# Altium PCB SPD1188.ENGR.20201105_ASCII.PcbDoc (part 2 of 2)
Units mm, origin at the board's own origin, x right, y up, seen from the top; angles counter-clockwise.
Board outline 110.11 x 115.1 mm, 2 copper layers (Top Layer, Bottom Layer); 167 components, 110 nets, 467 pads, 496 vias.
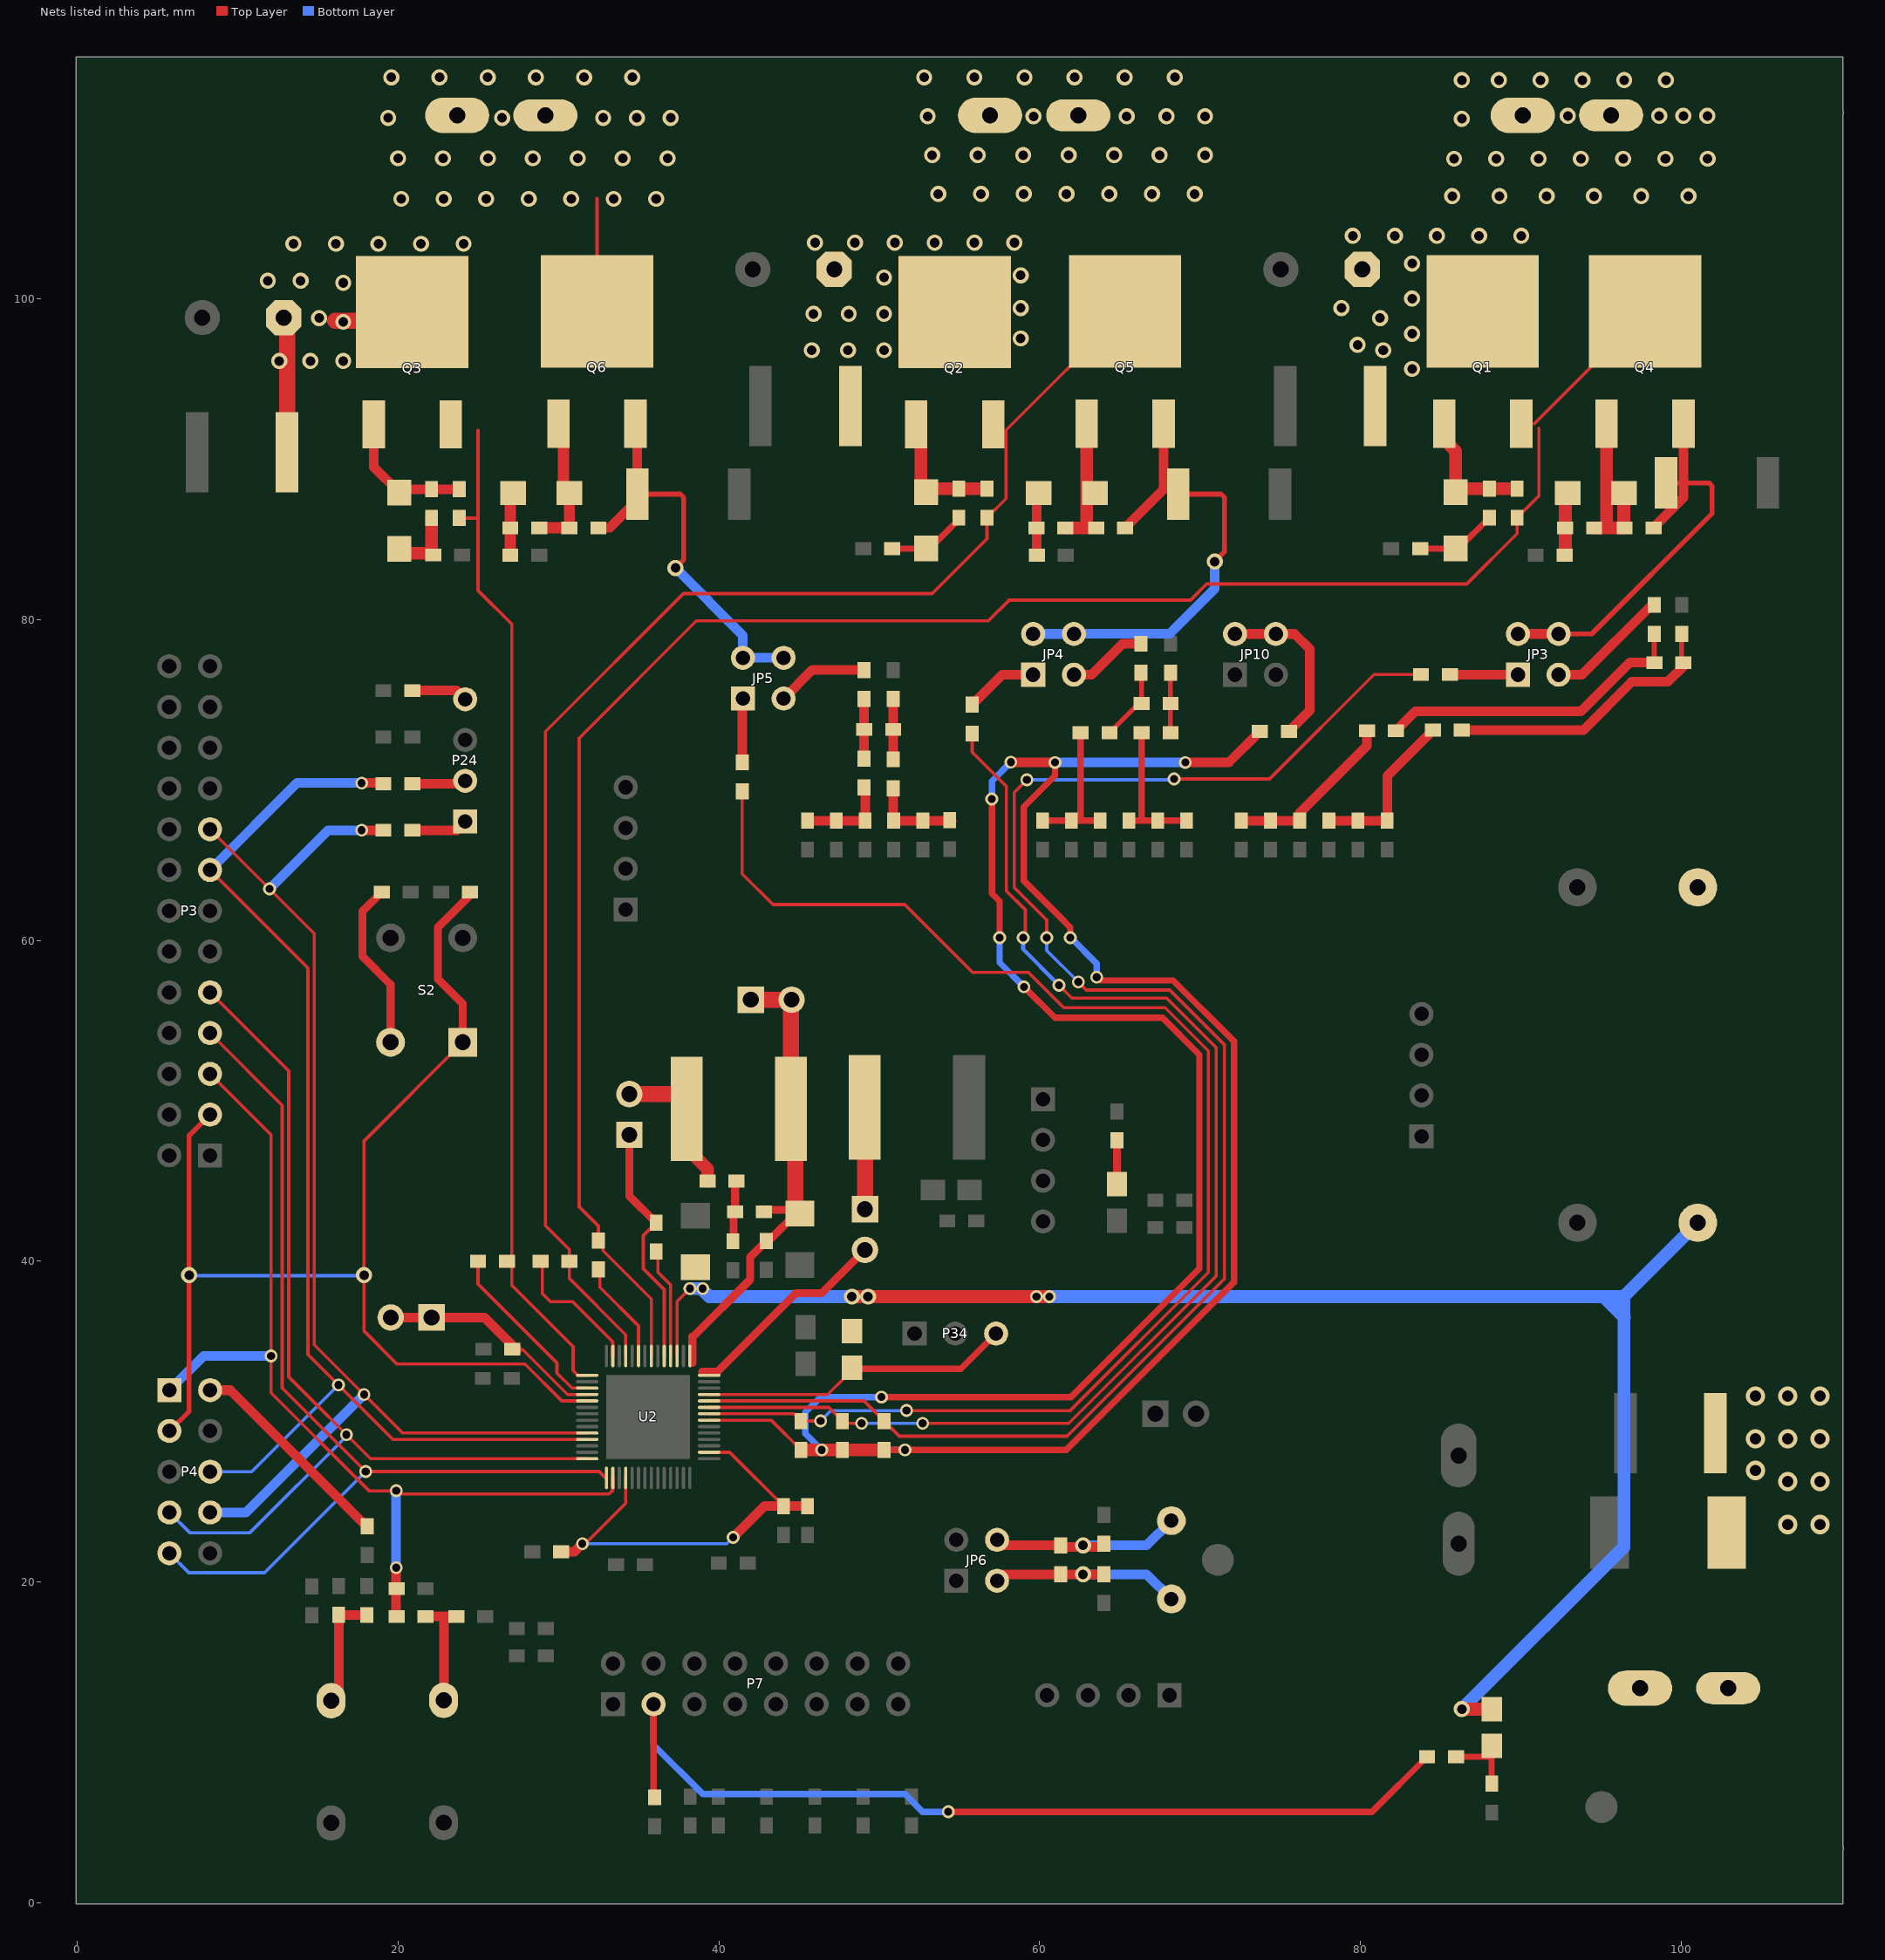
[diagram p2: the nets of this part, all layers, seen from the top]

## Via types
v1: diameter 0.8, hole 0.5, Top Layer to Bottom Layer, tented both sides, 215 vias
v2: diameter 1, hole 0.6, Top Layer to Bottom Layer, 161 vias
v3: diameter 1, hole 0.6, Top Layer to Bottom Layer, tented both sides, 71 vias
v4: diameter 1.2, hole 0.7, Top Layer to Bottom Layer, tented both sides, 33 vias
v5: diameter 0.8, hole 0.5, Top Layer to Bottom Layer, 16 vias

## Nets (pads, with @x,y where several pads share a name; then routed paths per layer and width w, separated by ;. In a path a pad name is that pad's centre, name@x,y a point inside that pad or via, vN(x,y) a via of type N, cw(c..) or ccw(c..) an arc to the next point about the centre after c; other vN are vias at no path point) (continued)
NetC58_1: C58.1 C60.1 R86.1 | length 3.7
  Top Layer w0.5: C60.1@40.93,41.38 C58.1@40.93,43.08 ; C58.1@41.02,43.08 41.02,44.92 R86.1@41.1,45
NetC130_1: C130.1 R133.1 R135.2 | length 19.6
  Top Layer w0.3: C130.1@98.29,77.31 R135.2@98.29,79.1
  Top Layer w0.6: R133.1@82.19,73.06 83.39,74.26 93.72,74.26 96.76,77.3 C130.1@98.28,77.3
NetC130_2: C130.2 R132.1 R134.2 | length 17.4
  Top Layer w0.3: C130.2@100,77.4 R134.2@100,79.1
  Top Layer w0.6: R132.1@86.3,73.1 93.88,73.1 96.89,76.11 99.14,76.11 100.1,77.07 C130.2@100.1,77.3
NetC140_1: C140.1 R143.1 R145.2 | length 4.7
  Top Layer w0.3: R143.1@64.35,72.94 66.17,74.76 C140.1@66.35,74.76 66.35,76.63 R145.2@66.3,76.68
NetC140_2: C140.2 R142.1 R144.2 | length 3.7
  Top Layer w0.3: R142.1@68.15,72.94 R144.2@68.15,76.68
NetC150_1: C150.1 R153.1 R155.2 | length 3.7
  Top Layer w0.6: R153.1@49.05,71.32 R155.2@49.05,75.04
NetC150_2: C150.2 R152.1 R154.2 | length 3.8
  Top Layer w0.6: R152.1@50.87,71.28 R154.2@50.87,75.04
NetC232_1: C232.1 R130.1 R132.2 R136.1 | length 10.5
  Top Layer w0.6: C232.1@78.011,67.45 R136.1@79.831,67.45 R130.1@81.65,67.45 81.65,70.25 R132.2@84.5,73.1
NetC233_2: C233.2 R131.1 R133.2 R194.1 | length 11
  Top Layer w0.6: R131.1@72.554,67.45 R194.1@74.373,67.45 C233.2@76.192,67.45 76.192,67.932 80.39,72.13 R133.2@80.39,73.06
NetC234_1: C234.1 R140.2 R143.2 R147.1 | length 9
  Top Layer w0.4: R140.2@60.184,67.45 C234.1@63.766,67.45 ; 62.55,67.49 R143.2@62.55,72.94
NetC235_2: C235.2 R141.1 R142.2 R146.1 | length 9
  Top Layer w0.4: C235.2@65.558,67.45 R141.1@69.14,67.45 ; 66.35,67.49 R142.2@66.35,72.94
NetC236_1: C236.1 R150.1 R152.2 R156.1 | length 5.6
  Top Layer w0.6: R152.2@50.87,69.48 50.87,67.498 50.918,67.45 R156.1@52.712,67.45 R150.1@54.506,67.45
NetC237_2: C237.2 R151.1 R153.2 R157.1 | length 5.7
  Top Layer w0.6: R151.1@45.535,67.45 R157.1@47.329,67.45 C237.2@49.123,67.45 49.123,69.447 R153.2@49.05,69.52
NetD1_1: D1.1 Q1.1 R2.2 RP1.1 | length 8.2
  Top Layer w0.8: Q1.1@85.2,92.19 85.2,91.2 85.916,90.484 D1.1@85.916,87.925 ; D1.1@86.125,88.135 RP1.1@89.741,88.135
NetD1_2: D1.2 R1.2 R2.1 | length 5.1
  Top Layer w0.4: R1.2@83.7,84.4 86.081,84.4 R2.1@88.016,86.335
NetD2_1: D2.1 Q2.1 R4.2 RP2.1 | length 7.9
  Top Layer w0.8: Q2.1@52.3,92.15 52.6,91.85 52.6,88.24 D2.1@52.8,88.04 ; D2.1@53.125,88.135 RP2.1@56.716,88.135
NetD2_2: D2.2 R3.2 R4.1 | length 5
  Top Layer w0.4: R3.2@50.8,84.4 53.141,84.4 R4.1@55.016,86.275
NetD3_1: D3.1 Q3.1 R6.2 Rp3.1 | length 8.4
  Top Layer w0.6: Q3.1@18.5,92.15 18.5,89.494 D3.1@20.094,87.9 ; D3.1@20.304,88.11 Rp3.1@23.826,88.11
NetD3_2: D3.2 R5.2 R6.1 | length 3.9
  Top Layer w0.8: D3.2@20.374,84.121 22.11,84.121 R6.1@22.11,86.31
NetD4_1: D4.1 Q4.1 R8.2 Rp4.1 | length 10.5
  Top Layer w0.8: R8.2@94.541,85.7 Rp4.1@96.441,85.7 ; 95.316,85.716 Q4.1@95.316,92.19 ; Rp4.1@96.391,85.75 D4.1@96.391,87.863
NetD4_2: D4.2 R7.2 R8.1 | length 3.7
  Top Layer w0.8: R7.2@92.741,84 D4.2@92.741,87.713
NetD5_1: D5.1 Q5.1 R10.2 Rp5.1 | length 7.8
  Top Layer w0.8: R10.2@61.593,85.7 62.916,85.7 ; 62.916,85.716 Q5.1@62.916,92.19
NetD5_2: D5.2 R9.2 R10.1 | length 3.7
  Top Layer w0.6: R9.2@59.816,84 D5.2@59.816,87.744
NetD6_1: D6.1 Q6.1 R12.2 Rp6.1 | length 8
  Top Layer w0.7: R12.2@28.81,85.7 Rp6.1@30.7,85.7 30.693,85.707 D6.1@30.693,87.583 ; D6.1@30.316,88.54 Q6.1@30.316,92.19 ; D6.1@30.693,87.863 D6.1@30.693,87.583 ; D6.1@30.91,87.8 D6.1@30.693,87.583
NetD6_2: D6.2 R11.2 R12.1 | length 3.7
  Top Layer w0.7: R11.2@27.01,84 D6.2@27.01,87.68
NetD7_2: D7.2 R16.2 | length 2.7
  Top Layer w0.5: D7.2@64.81,44.813 R16.2@64.81,47.53
NetJP2_1: JP2.1 L2.1 | length 7.1
  Top Layer w1: L2.1@48.59,49.59 L2.1@49.09,49.09 ; L2.1@49.09,49.59 L2.1@49.09,49.09 ; JP2.1@49.11,43.25 49.11,47.28 49.09,47.3 L2.1@49.09,49.09
NetJP3_1: JP3.1 R187.1 | length 4.2
  Top Layer w0.6: R187.1@85.55,76.56 89.78,76.56 JP3.1@89.79,76.55
NetJP3_3: JP3.3 R135.1 | length 7.8
  Top Layer w0.6: JP3.3@92.33,76.55 93.79,76.55 98.14,80.9 R135.1@98.29,80.9
NetJP4_1: JP4.1 R188.1 | length 4.6
  Top Layer w0.6: R188.1@55.79,74.68 57.66,76.55 JP4.1@59.59,76.55
NetJP4_3: JP4.3 R145.1 | length 5
  Top Layer w0.6: JP4.3@62.13,76.55 63.23,76.55 65.16,78.48 R145.1@66.3,78.48
NetJP5_1: JP5.1 R189.1 | length 3.7
  Top Layer w0.6: R189.1@41.46,71.32 JP5.1@41.46,75.02
NetJP5_3: JP5.3 R155.1 | length 5.7
  Top Layer w0.6: JP5.3@44.04,75.06 45.82,76.84 R155.1@49.05,76.84
NetJP10_2: JP10.2 JP10.4 R137.1 | length 10.7
  Top Layer w0.6: JP10.2@72.17,79.09 JP10.4@74.71,79.09 75.87,79.09 76.81,78.15 76.81,74.31 R137.1@75.52,73.02
NetP4_2: P4.2 R68.1 | length 13.3
  Top Layer w0.6: P4.2@8.31,31.97 9.557,31.97 18.027,23.5 R68.1@18.1,23.5
NetP24_4: P24.4 R24.1 | length 3.5
  Top Layer w0.6: R24.1@20.9,75.565 23.655,75.565 P24.4@24.2,75.02
NetR31_2: R31.2 R32.2 S3.1 | length 7.3
  Top Layer w0.6: R31.2@21.76,17.89 R32.2@23.646,17.89 ; S3.1@22.88,12.4 22.88,17.816
NetR61_2: R61.2 R77.2 S1.1 | length 7.5
  Top Layer w0.6: S1.1@15.87,12.38 15.87,12.7 16.32,13.15 R61.2@16.32,17.97 18.06,17.97 R77.2@18.07,17.96
NetR66_1: R66.1 S2.2 | length 10.6
  Top Layer w0.5: R66.1@19,63 17.8,61.8 17.8,59 19.55,57.25 S2.2@19.55,53.65
NetR440_1: R440.1 R441.2 R442.2 | length 4.5
  Top Layer w0.381: R442.2@85.93,9.13 R440.1@88.09,9.13 ; R441.2@88.16,7.45 R440.1@88.16,9.807
PX_U: C13.2 Q3.3 Q6.2 Rp3.2 U1.1 U2.43 | length 70.3
  Top Layer w0.2: Rp3.2@23.826,86.31 24.99,86.31 ; 25,91.774 25,81.8 27.1,79.7 27.1,38.5 30.92,34.68 30.92,33.19 31.21,32.9 U2.43@31.8,32.9 ; Q6.2@32.416,99.19 32.416,106.24
  other v2: 20.216,106.2 22.863,106.2 25.51,106.2 28.158,106.2 30.805,106.2 33.453,106.2 36.1,106.2 20.016,108.722 22.816,108.722 25.616,108.722 28.416,108.722 31.216,108.722 34.016,108.722 36.816,108.722 19.4,111.245 26.5,111.245 32.8,111.245 34.9,111.245 37,111.245 19.6,113.767 22.603,113.767 25.606,113.767 28.609,113.767 31.613,113.767 34.616,113.767
PX_V: C14.2 Q2.3 Q5.2 RP2.2 U2.39 V1.1 | length 91.2
  Top Layer w0.2: U2.39@34.2,34.1 34.2,35.42 30.7,38.92 C14.2@30.7,40 30.7,40.723 29.2,42.223 29.2,73 37.8,81.6 53.3,81.6 56.716,85.016 RP2.2@56.716,86.335 57.9,87.519 57.9,91.774 Q5.2@65.316,99.19
  other v2: 53.672,106.5 56.336,106.5 59,106.5 61.664,106.5 64.328,106.5 66.992,106.5 69.656,106.5 53.3,108.922 56.133,108.922 58.967,108.922 61.8,108.922 64.633,108.922 67.467,108.922 70.3,108.922 53.016,111.345 59.616,111.345 65.416,111.345 67.9,111.345 70.3,111.345 52.8,113.767 55.923,113.767 59.046,113.767 62.169,113.767 65.293,113.767 68.416,113.767
PX_W: C15.2 Q1.3 Q4.2 RP1.2 U2.35 W1.1 | length 121.1
  Top Layer w0.2: U2.35@35.8,34.1 35.8,37.65 32.79,40.66 32.79,41.01 C15.2@32.5,41.3 32.5,42.2 31.3,43.4 31.3,72.6 38.6,79.9 56.8,79.9 58.1,81.2 69.4,81.2 70.4,82.2 86.6,82.2 89.741,85.341 RP1.2@89.741,86.335 91.1,87.694 91.1,91.906 ; 90.816,92.19 97.716,99.09 Q4.2@97.716,99.19
  other v2: 85.7,106.367 88.643,106.367 91.586,106.367 94.529,106.367 97.472,106.367 100.416,106.367 85.816,108.7 88.449,108.7 91.082,108.7 93.716,108.7 96.349,108.7 98.982,108.7 101.616,108.7 86.3,111.189 92.9,111.367 98.6,111.367 100.1,111.367 101.6,111.367 86.3,113.6 88.603,113.6 91.206,113.6 93.809,113.6 96.412,113.6 99.016,113.6
RU: JP5.2 JP5.4 Q6.3 R15.2 Rp6.2 | length 25
  Top Layer w0.3: R15.2@34.925,87.8 37.6,87.8 37.8,87.6 37.8,83.7 v3(37.3,83.2)
  Top Layer w0.6: Rp6.2@32.5,85.7 33.214,85.7 R15.2@34.925,87.411 ; Q6.3@34.816,92.19 34.925,92.081 R15.2@34.925,87.8
  Bottom Layer w0.6: v3(37.3,83.2) 41.5,79 JP5.2@41.5,77.6 JP5.4@44.04,77.6
RV: JP4.2 JP4.4 Q5.3 R14.2 Rp5.2 | length 28.9
  Top Layer w0.3: R14.2@68.625,87.8 71.3,87.8 71.5,87.6 71.5,84.2 v3(70.9,83.6)
  Top Layer w0.6: Rp5.2@65.316,85.7 67.716,88.1 Q5.3@67.716,92.19
  Bottom Layer w0.6: JP4.2@59.59,79.09 JP4.4@62.13,79.09 62.14,79.1 68.1,79.1 70.9,81.9 v3(70.9,83.6)
RW: JP3.2 JP3.4 Q4.3 R13.2 Rp4.2 | length 27.1
  Top Layer w0.3: JP3.4@92.33,79.09 94.39,79.09 101.9,86.6 101.9,88.3 101.7,88.5 R13.2@99.025,88.5
  Top Layer w0.6: JP3.2@89.79,79.09 JP3.4@92.33,79.09 ; Rp4.2@98.241,85.7 100.116,87.575 Q4.3@100.116,92.19
RXD: P3.15 P4.6 R73.2 U2.53 | length 75.9
  Top Layer w0.2: P3.15@8.3,64.38 14.4,58.28 14.4,34.2 19.7,28.9 U2.53@31.8,28.9
  Top Layer w0.6: v1(17.75,69.8) 18.922,69.8 19.022,69.7 19.082,69.76 19.142,69.7 R73.2@19.2,69.758
  Bottom Layer w0.2: P4.6@8.31,26.89 10.89,26.89 v1(16.3,32.3)
  Bottom Layer w0.6: P3.15@8.3,64.38 13.72,69.8 v1(17.75,69.8) ; P3.15@8.422,64.258 P3.15@8.48,64.2
SNS_GND: C131.2 C191.2 C192.2 R137.2 U2.21 | length 174.2
  Top Layer w0.2: U2.21@39.4,30.1 43.27,30.1 43.32,30.05 ; 44.233,29.137 43.32,30.05 ; C131.2@45.12,28.25 43.32,30.05
  Top Layer w0.4: v1(50.14,31.54) 57.041,31.54 61.94,31.54 69.945,39.545 69.945,52.871 67.649,55.167 60.948,55.167 v1(59.016,57.1) ; C191.2@50.3,28.25 56.85,28.25 61.65,28.25 72.1,38.7 72.1,53.7 68.3,57.5 63.75,57.5 v1(63.55,57.7) ; v1(57.016,68.8) 57.016,62.911 57.5,62.427 v1(57.5,60.167) ; v1(60.95,71.08) 60.95,70.25 59.02,68.32 59,68.3 59,63.7 61.2,61.5 61.9,60.8 v1@61.9,60.2
  Top Layer w0.6: v1(58.2,71.1) 58.22,71.08 v1(60.95,71.08) ; v1(69.07,71.08) 71.78,71.08 R137.2@73.72,73.02
  Top Layer w0.8: C131.2@45.12,28.25 C192.2@47.71,28.25 C191.2@50.3,28.25
  Bottom Layer w0.4: v1(50.14,31.54) 46.34,31.54 45.4,30.6 45.4,29.265 v1(46.415,28.25) v1(51.6,28.25) ; v1(57.016,68.8) 57.016,69.916 v1(58.2,71.1) ; v1(57.5,60.167) 57.5,58.616 v1(59.016,57.1) ; v1@61.9,60.2 63.55,58.55 63.55,57.85 v1@63.625,57.775
  Bottom Layer w0.6: v1(60.95,71.08) v1(69.07,71.08)
  other v1: 61.9,60.167
SNSP_U: C131.1 R189.2 U2.22 | length 87.9
  Top Layer w0.2: U2.22@39.4,30.5 44.67,30.5 C131.1@45.12,30.05 v1(46.35,30.05) ; R189.2@41.46,69.52 41.46,64.15 43.38,62.23 51.586,62.23 55.816,58 59.3,58 61.5,55.8 67.815,55.8 70.51,53.105 70.51,39.31 61.9,30.7 v1(51.7,30.7)
  Bottom Layer w0.2: v1(46.35,30.05) 47,30.7 v1(51.7,30.7)
SNSP_V: C192.1 R188.2 U2.23 | length 79.5
  Top Layer w0.2: U2.23@39.4,30.9 46.86,30.9 C192.1@47.71,30.05 ; C192.1@47.97,29.9 v1(48.9,29.9) ; v1(52.7,29.9) 61.807,29.9 71,39.093 71,53.308 67.908,56.4 62,56.4 v1(61.2,57.2) ; R188.2@55.885,72.615 55.97,72.7 R188.2@55.79,72.88 55.79,71.726 57.926,69.59 57.926,63.074 59.1,61.9 v1@59.1,60.2
  Bottom Layer w0.2: v1(48.9,29.9) v1(52.7,29.9) ; v1@59.1,60.167 v1@59.1,60.2 ; v1@61.1,57.3 v1(61.2,57.2)
  Bottom Layer w0.25: v1(58.967,60.167) 58.967,59.433 v1@61.1,57.3
SNSP_W: C191.1 R187.2 U2.24 | length 104.5
  Top Layer w0.2: U2.24@39.4,31.3 49.05,31.3 C191.1@50.3,30.05 51.25,29.1 61.7,29.1 71.5,38.9 71.5,53.501 68.101,56.9 62.9,56.9 v1(62.4,57.4) ; v1(59.2,70) 58.416,69.216 58.416,63.285 60.433,61.268 60.433,60.367 v1@60.6,60.2 ; v1(68.37,70.05) 74.32,70.05 80.83,76.56 R187.2@83.75,76.56
  Bottom Layer w0.2: v1(59.2,70) 68.32,70 v1(68.37,70.05) ; v1(60.433,60.167) v1@60.433,60.033 ; v1@60.6,60.2 v1@60.433,60.033 ; v1(62.4,57.4) 60.433,59.367 v1@60.433,60.033
SW3: JP2.2 U2.28 | length 13.3
  Top Layer w0.5: 38.96,33.11 39.91,33.11 44.82,38.02 46.42,38.02 JP2.2@49.11,40.71
SWCK: P3.7 P4.9 U2.1 | length 61.8
  Top Layer w0.2: P3.7@8.3,54.22 12.8,49.72 12.8,32.1 v1(18,26.9) 32.56,26.9 U2.1@32.96,26.5
  Bottom Layer w0.2: P4.9@5.77,21.81 6.98,20.6 11.7,20.6 v1(18,26.9)
SWDIO: P3.9 P4.7 U2.56 | length 60.8
  Top Layer w0.2: P3.9@8.3,56.76 13.2,51.86 13.2,32.8 18.3,27.7 U2.56@31.8,27.7
  Bottom Layer w0.2: P4.7@5.77,24.35 7.03,23.09 10.79,23.09 16.8,29.1 v1(16.8,29.2)
SWG: C51.1 JP1.1 U2.33 | length 15.6
  Top Layer w0.2: C51.1@36.09,42.69 36.09,42.39 35.3,41.6 35.3,39.537 36.6,38.237 U2.33@36.6,34.1
  Top Layer w0.5: JP1.1@34.43,47.88 34.43,44.07 C51.1@36.1,42.4
SWG1: JP1.2 L1.1 R86.2 | length 12.1
  Top Layer w0.5: L1.1@38.22,47.9 L1.1@38.22,49.19
  Top Layer w0.8: L1.1@37.92,46.68 37.92,49.42 L1.1@38,49.5 38,47.05 39.3,45.75 R86.2@39.3,45
  Top Layer w1: JP1.2@35.03,50.42 L1.1@37.92,50.42
TRSTN: CL8.1 P3.5 P4.1 R31.1 U2.2 | length 61.3
  Top Layer w0.2: P3.5@8.3,51.68 12.1,47.88 12.1,31.8 18.2,25.7 v1(19.9,25.7) 20.1,25.5 33.166,25.5 33.4,25.734 U2.2@33.4,26.5
  Top Layer w0.6: v1(19.9,20.91) 19.9,17.883 R31.1@19.923,17.86
  Bottom Layer w0.6: P4.1@5.77,31.97 7.9,34.1 v1(12.1,34.1) ; v1(19.9,20.91) v1(19.9,25.7)
TXD: P3.17 P4.8 R74.2 U2.52 | length 75.4
  Top Layer w0.2: P3.17@8.3,66.92 14.8,60.42 14.8,34.8 20.3,29.3 U2.52@31.8,29.3
  Top Layer w0.6: v1(17.75,66.86) 19.015,66.86 19.055,66.9 R74.2@19.1,66.855
  Bottom Layer w0.6: P4.8@8.31,24.35 10.55,24.35 v1(17.9,31.7) ; v1(12.01,63.21) 15.66,66.86 v1(17.75,66.86)
UART_RXD: P24.2 R73.1 | length 3.4
  Top Layer w0.6: R73.1@20.9,69.758 24.018,69.758 P24.2@24.2,69.94
UART_TXD: P24.1 R74.1 | length 3.5
  Top Layer w0.6: R74.1@20.9,66.855 23.655,66.855 P24.1@24.2,67.4
VBAT: C1.1 C2.1 C4.1 C5.1 C6.1 C9.1 C70.1 C72.1 C79.2 E1.1 E2.1 Q1.2 Q2.2 Q3.2 R440.2 U2.31 Vin+.1 ZD1.1 | length 120
  Top Layer w0.2: U2.31@37.4,34.1 37.4,37.5 v1(38.2,38.3)
  Top Layer w0.8: v3(48.3,37.8) v3(49.3,37.8) v1(59.8,37.8) v1(60.6,37.8) ; v3(86.3,12.1) 86.307,12.093 R440.2@88.16,12.093
  Top Layer w1: C6.1@13.1,90.4 C9.1@13.1,98.6 ; 16.1,98.6 22.326,98.6 Q3.2@22.916,99.19
  Bottom Layer w0.8: v1(38.2,38.3) 38.9,38.3 39.4,37.8 v3(48.3,37.8) v3(49.3,37.8) ; v1(59.8,37.8) v1(60.6,37.8) 96.4,37.8 ; v3(86.3,12.1) 96.4,22.2 96.4,36.516 ; 95.174,37.741 96.4,36.516 ; 96.416,36.5 96.4,36.516 ; E1.1@101,42.4 96.4,37.8 ; 96.4,36.516 96.4,37.8
  other v1: 39,38.3
  other v2: 83.2,95.6 12.616,96.1 14.558,96.1 16.6,96.1 45.8,96.767 48.05,96.767 50.3,96.767 81.4,96.767 79.8,97.1 58.816,97.5 83.2,97.789 16.6,98.533 15.1,98.767 81.2,98.767 45.9,99.034 48.1,99.034 50.3,99.034 78.8,99.4 58.816,99.401 83.2,99.978 16.6,100.967 11.9,101.1 13.95,101.1 50.3,101.301 58.816,101.434 83.2,102.167 13.5,103.4 16.15,103.4 18.8,103.4 21.45,103.4 24.1,103.4 46,103.467 48.483,103.467 50.966,103.467 53.449,103.467 55.933,103.467 58.416,103.467 79.5,103.9 82.125,103.9 84.75,103.9 87.375,103.9 90,103.9
  other v4: 106.608,23.6 108.616,23.6 106.608,26.267 108.616,26.267 104.6,26.967 104.6,28.933 106.608,28.933 108.616,28.933 104.6,31.6 106.608,31.6 108.616,31.6
VBAT_DIV: CL420.2 P7.3 R442.1 | length 59.6
  Top Layer w0.4: P7.3@35.94,12.4 35.94,6.66 CL420.2@36,6.6 ; v1@54.4,5.7 80.7,5.7 R442.1@84.13,9.13
  Bottom Layer w0.4: P7.3@35.94,12.4 35.94,9.86 39,6.8 51.6,6.8 52.7,5.7 v1(54.3,5.7)
VBOOT_U: C13.1 U2.45 | length 11.3
  Top Layer w0.2: C13.1@25,40 25,38.59 29.92,33.67 29.92,33.03 30.85,32.1 U2.45@31.8,32.1
VBOOT_V: C14.1 U2.41 | length 8.5
  Top Layer w0.2: C14.1@29,40 29,38 29.51,37.49 30.9,37.49 33.4,34.99 U2.41@33.4,34.1
VBOOT_W: C15.1 U2.37 | length 6.4
  Top Layer w0.2: C15.1@32.6,39.5 32.6,38.38 35,35.98 U2.37@35,34.1
VBOOTG: C51.2 U2.32 | length 7.1
  Top Layer w0.2: C51.2@36.2,40.9 36.2,39.33 37,38.53 U2.32@37,34.1
VCAP12: C25.2 CL53.2 CL54.2 U2.4 U2.16 | length 27.7
  Top Layer w0.2: v1@31.593,22.307 34.2,24.914 U2.4@34.2,26.5 ; U2.16@39.4,28.1 40.68,28.1 CL53.2@44.03,24.75
  Top Layer w0.6: C25.2@30.18,21.9 31,21.9 v1(31.5,22.4) ; v1(40.9,22.8) 42.85,24.75 CL53.2@43.957,24.75 ; CL53.2@44.03,24.75 CL54.2@45.53,24.75
  Bottom Layer w0.2: v1(31.5,22.4) 40.5,22.4 v1(40.9,22.8)
VCP: C79.1 P34.3 U2.25 | length 18.7
  Top Layer w0.2: U2.25@39.4,31.7 46.785,31.7 C79.1@47.942,32.858
  Top Layer w0.4: C79.1@48.495,33.3 55.08,33.3 P34.3@57.28,35.5
VDD5: C54.2 P38.1 P38.2 U2.46 | length 14.2
  Top Layer w0.2: C54.2@27.445,34.5 27.79,34.5 30.59,31.7 U2.46@31.8,31.7
  Top Layer w0.6: P38.2@19.56,36.5 19.57,36.49 25.41,36.49 27.4,34.5 C54.2@27.445,34.5
VDDG: C58.2 C62.2 C71.1 L1.2 P36.1 P36.2 U2.29 | length 28.8
  Top Layer w0.5: 38.35,33.665 38.35,35.31 ; 38.415,35.315 41.96,38.86 41.96,40.26 C62.2@42.96,41.26 ; C58.2@42.8,43.08 42.92,43.2 C71.1@44.88,43.2 ; C62.2@43.1,41.26 C71.1@44.96,43.12
  Top Layer w1: P36.1@42,56.3 P36.2@44.46,56.3 ; L1.2@44.5,47.83 44.768,47.562 C71.1@44.768,43.032 ; L1.2@44.5,49.5 P36.2@44.5,56.26 ; C71.1@44.88,43.2 C71.1@44.96,43.12 ; C71.1@45.048,43.032 C71.1@45.108,42.972 ; P36.2@44.46,56.3 P36.2@44.5,56.26 ; P36.2@44.46,56.3 P36.2@44.54,56.3 P36.2@44.5,56.26
XIN: CL65.2 JP6.3 R102.1 Y1.1 | length 13.1
  Top Layer w0.6: JP6.3@57.34,19.9 JP6.3@57.44,20 ; JP6.3@57.34,20.1 57.74,20.5 R102.1@61.3,20.5 CL65.2@64,20.5
  Bottom Layer w0.6: v3(62.7,20.5) 66.66,20.5 Y1.1@68.2,18.96
XIO: CL66.2 JP6.4 R102.2 Y1.2 | length 13.1
  Top Layer w0.6: JP6.4@57.34,22.44 57.7,22.44 57.84,22.3 R102.2@61.2,22.3 ; R102.2@61.3,22.3 R102.2@61.2,22.3 ; CL66.2@64,22.4 63.8,22.2 61.3,22.2 R102.2@61.2,22.3
  Bottom Layer w0.6: v3(62.7,22.3) 66.66,22.3 Y1.2@68.2,23.84
XRSTN: CL3.2 P3.3 P4.3 S2.1 U2.47 | length 78.7
  Top Layer w0.2: S2.1@24.05,53.65 17.9,47.5 17.9,39.1 17.9,35.649 19.949,33.6 27.92,33.6 30.22,31.3 U2.47@31.8,31.3
  Top Layer w0.3: P4.3@5.77,29.43 7,30.66 v3(7,39.14) 7,47.84 P3.3@8.3,49.14
  Top Layer w0.5: S2.1@24.05,53.65 24.05,56.05 22.5,57.6 22.5,60.8 24.5,62.8 CL3.2@24.5,63
  Bottom Layer w0.2: v3(7,39.14) 7.04,39.1 v3@17.9,39.1
  other v3: 17.9,39.14
pads on no net: P3.19 P4.5 P7.1 S2.3 S2.4

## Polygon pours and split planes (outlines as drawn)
GND on Top Layer "Bottom Layer-W" (hatched 90Degree grid 0.2 track 0.2, remove dead copper, pour order 55): 72.8,104.4 72.8,85.5 73.5,84.8 77.333,84.8 77.9,85.367 77.9,86.3 77.9,95.4 76.9,96.4 76.9,99.1 76.9,104.4 76.3,105 75.8,105 73.4,105
RV on Top Layer "Bottom Layer-W" (hatched 90Degree grid 0.2 track 0.2, remove dead copper, pour order 53): 65.9,86.45 65.9,93.6 66.2,93.9 66.3,94 70.2,94 70.8,93.4 70.8,86 70.2,85.4 65.8,85.4 65.6,85.6 65.6,85.984
PX_V on Top Layer "Bottom Layer-W" (hatched 90Degree grid 0.2 track 0.2, remove dead copper, pour order 52): 55.6,91 55.6,94.4 55.8,94.6 56.2,95 56.8,95 58.5,95 60.2,96.7 60.2,104 59.3,104.9 58.7,105.5 53.8,105.5 53,106.3 52.1,107.2 52.1,109.3 52.1,113.9 52.8,114.6 55.1,114.6 68.6,114.6 70.4,112.8 70.8,112.4 70.8,96.3 70.8,96.2 70,95.4 69.3,94.7 67.4,94.7 62.2,94.7 61.1,93.6 61.1,92 61.1,90.6 60.2,89.7 59.5,89.7 58.4,89.7 57.9,89.2 57.4,89.7 56.9,89.7 56.1,89.7 55.6,90.2
VBAT on Top Layer "Bottom Layer-W" (hatched 90Degree grid 0.2 track 0.2, remove dead copper, pour order 51): 45.1,87.5 45.1,103.6 45.7,104.2 51,104.2 58.6,104.2 59.4,103.4 59.4,97.2 58,95.8 57.7,95.8 51.8,95.8 50.7,94.7 50.7,87.5 49.8,86.6 47.3,86.6 46,86.6
RU on Top Layer "Bottom Layer-W" (hatched 90Degree grid 0.2 track 0.2, remove dead copper, pour order 49): 33.5,86.2 33.5,93.4 33.8,93.7 34,93.9 34.9,93.9 36.6,93.9 37,93.5 37.2,93.3 37.2,85.5 36.6,84.9 34.7,84.9 34.2,85.4 32.7,85.4
GND on Top Layer "Bottom Layer-W" (hatched 90Degree grid 0.2 track 0.2, remove dead copper, pour order 47): 38.9,88 38.9,105.3 39.9,106.3 42.8,106.3 43.8,105.3 44.2,104.9 44.2,99.1 44.2,85.7 43.4,84.9 41.8,84.9 39.7,84.9 38.9,85.7
PX_U on Top Layer "Bottom Layer-W" (hatched 90Degree grid 0.2 track 0.2, remove dead copper, pour order 43): 25,84.9 24.9,84.9 23.8,86 23.826,86.026 23.826,86.31 23.826,86.326 24.5,87 24.8,87.3 24.8,89 24.4,89.4 23.5,89.4 22.6,89.4 22.2,89.8 22.2,91.3 22.2,93.3 22.3,93.4 22.7,93.8 23.7,93.8 26.4,96.5 26.4,103.8 24.7,105.5 20.1,105.5 19,106.6 18.3,107.3 18.3,109.6 18.3,113.3 18.5,113.5 19.5,114.5 22.6,114.5 34.9,114.5 36.4,113 37.7,111.7 37.7,100.8 37.7,96.3 36.6,95.2 36,94.6 28.9,94.6 28.3,94 28.3,92.1 28.3,90.4 28.1,90.2 27.8,89.9 27.4,89.9 26,89.9 25.4,89.3 25.3,89.2 25.3,88.6 25.3,81.1 25,81.4 25,82
VBAT on Top Layer "Bottom Layer-W" (hatched 90Degree grid 0.2 track 0.2, remove dead copper, pour order 42): 11.3,87.6 11.3,102.2 12.7,103.6 13.5,104.4 18.6,104.4 24.5,104.4 25.4,103.5 25.4,96.5 23.6,94.7 17.8,94.7 17,93.9 17,87.7 16.8,87.5 16.2,86.9 14.8,86.9 12,86.9
AGND on Top Layer "Bottom Layer-No Net 1" (hatched 90Degree grid 0.203 track 0.203, remove dead copper, pour order 39): 33.47,18.51 33.61,18.65 34.18,18.65 34.34,18.65 34.93,19.24 34.93,21.17 34.93,21.38 35.08,21.53 35.77,22.22 35.77,22.27 35.77,18.37 35.367,17.967 35.3,17.9 34.91,17.9 33.42,17.9 33.25,18.07
GND on Top Layer "Top Layer-No Net" (hatched 90Degree grid 0.2 track 0.2, remove dead copper, pour order 63): 54.016,68.78 54.143,68.78 54.92,68.78 55.3,68.4 55.3,67.567 55.3,61.4 55.7,61 55.933,60.767 56.4,60.767 56.686,60.767 56.816,60.897 57.016,61.097 57.016,61.5 57.016,62.752 56.8,62.967 56.8,66.967 56.8,70.067 54.3,72.567 53.63,71.897 53.63,70.88 53.63,69.32 53.74,69.21
AGND on Top Layer "Top Layer-No Net" (hatched 90Degree grid 0.2 track 0.2, remove dead copper, pour order 61): 75.1,63.99 75.1,63.4 75.1,57.2 76.2,56.1 76.5,55.8 76.5,52.2 76.5,12.3 74.9,10.7 74.6,10.4 74.6,9.2 74.6,7.9 75,7.5 76.4,7.5 78.3,7.5 78.5,7.7 79.4,8.6 79.4,11.2 79.4,63.51 77.9,65.01 77.9,65.9 77.01,65.9
GND on Top Layer "Bottom Layer-No Net 1" (hatched 90Degree grid 0.2 track 0.2, remove dead copper, pour order 59): 77.69,76.232 78.082,75.84 79.416,75.84 79.5,75.814 81.209,77.53 87.503,77.53 87.94,77.967 88.216,78.243 88.216,80.036 88.747,80.567 93.987,80.567 94.3,80.88 94.3,81.59 94.1,81.79 92.9,81.79 89.1,81.79 88.25,81.79 87.3,80.84 78.433,80.84 77.69,80.097
GND on Top Layer "Bottom Layer-No Net 1" (hatched 90Degree grid 0.2 track 0.2, remove dead copper, pour order 58): 68.84,68.54 75.8,68.54 78.04,70.78 81.16,73.9 82.05,73.9 82.27,73.9 82.95,74.58 83.03,74.66 83.03,75.14 83.03,75.45 82.6,75.88 82.26,76.22 81.65,76.22 80.95,76.22 80.36,75.63 74.62,69.89 70.48,69.89 69.11,69.89 68.76,69.54 68.52,69.3 68.52,69.14 68.52,68.85 68.84,68.53
GND on Top Layer "Bottom Layer-No Net 1" (hatched 90Degree grid 0.2 track 0.2, remove dead copper, pour order 57): 57.98,75.14 63.19,75.13 64.18,76.12 64.81,76.12 65.1,75.83 65.24,75.69 65.24,75.08 65.24,74.46 64.9,74.12 64.79,74.01 63.08,74.01 61.8,74.01 61.34,73.55 59.78,71.99 57.45,71.99 56.82,72.62 56.82,74.56 57.23,74.97 57.4,75.14
GND on Top Layer "Bottom Layer-No Net 1" (hatched 90Degree grid 0.2 track 0.2, remove dead copper, pour order 56): 52.12,68.93 52.12,78.07 52.35,78.3 52.66,78.61 53.89,78.61 57.31,78.61 57.32,78.6 57.8,78.12 57.8,77.8 57.8,77.48 57.37,77.05 54.69,74.37 54.69,72.53 54.69,69.327 54.143,68.78 53.48,68.78 52.27,68.78
VBAT on Top Layer "Bottom Layer-No Net 1" (hatched 90Degree grid 0.2 track 0.2, remove dead copper, pour order 40): 93.9,14.6 101,21.7 101,30.9 101,31.6 101.7,32.3 102.1,32.7 105.9,32.7 108.4,32.7 109.1,32 109.1,27.1 109.1,12.6 107,10.5 106.7,10.2 103.1,10.2 95.9,10.2 93.9,12.2
GND on Top Layer "Bottom Layer-No Net 1" (hatched 90Degree grid 0.2 track 0.2, remove dead copper, pour order 45): 102,76.3 102,76.85 109,76.85 109,36.3 108.5,35.8 107.067,34.367 100.867,34.367 99.4,32.9 97.1,30.6 97.1,20.8 96.6,20.3 94.6,18.3 84.7,18.3 83.3,19.7 83.3,29.5 84.4,30.6 84.7,30.9 88,30.9 89.3,29.6 92.4,26.5 93.5,26.5 93.9,26.9 93.9,33.6 93.1,34.4 89.1,38.4 89.1,63.4 90.3,64.6
GND on Top Layer "Bottom Layer-No Net 1" (hatched 90Degree grid 0.2 track 0.2, remove dead copper, pour order 46): 97.3,75.5 96.9,75.5 96.7,75.5 96.3,75.1 93.9,72.7 91.6,72.7 84.6,72.7 83.5,71.6 82.1,70.2 82.1,68.7 82.1,64.2 80.6,62.7 80.2,62.3 80.2,60.4 80.2,9 80.9,8.3 81,8.2 81.9,8.2 82.4,8.7 82.8,9.1 82.8,10.2 82.8,14.5 82.4,14.9 81.9,15.4 81.9,23 81.9,31.8 83.2,33.1 86,33.1 87.2,34.3 87.8,34.9 87.8,60.5 87.8,63.4 91.8,67.4 98.3,73.9 98.3,74.5
GND on Top Layer "Bottom Layer-No Net 1" (hatched 90Degree grid 0.2 track 0.2, remove dead copper, pour order 44): 87.451,40.619 88.133,41.3 88.7,41.3 89.1,40.9 89.5,40.9 89.5,43.167 89.267,43.4 89.216,43.4 89.216,43.283 88.733,42.8 88.2,42.8 87.5,43.5 87.5,41.567 86.038,40.105
AGND on Top Layer "Bottom Layer-No Net 1" (hatched 90Degree grid 0.2 track 0.2, remove dead copper, pour order 48): 33.216,5.4 31.9,6.716 31.9,18.16 30.77,19.29 30.29,19.29 28.73,17.73 28.73,10.47 28.73,3.78 29.51,3 33.5,3 79.1,3 79.5,3.4 79.5,4.367 79.5,4.5 79.1,4.9 78.616,4.9 53.767,4.9 53.3,5.367 53.267,5.4
VBAT on Top Layer "Bottom Layer-W" (hatched 90Degree grid 0.2 track 0.2, remove dead copper, pour order 64): 79.2,88.5 79.2,96.6 78.1,97.7 78.1,101.9 78.1,103.3 79.5,104.7 88.8,104.7 91.4,104.7 91.7,104.4 91.7,96.4 90.9,95.6 85.1,95.6 83.8,94.3 83.8,89.1 82.8,88.1 82.5,87.8 80.5,87.8 79.7,87.8 79.2,88.3
PX_W on Top Layer "Bottom Layer-W" (hatched 90Degree grid 0.2 track 0.2, remove dead copper, pour order 65): 88.6,91 88.6,93.8 88.9,94.1 89.6,94.8 91.1,94.8 92.6,96.3 92.6,104.8 92.1,105.3 91.7,105.7 90.9,105.7 85.5,105.7 84.9,106.3 84.9,107.6 84.9,113.1 85.6,113.8 85.9,114.1 87.4,114.1 99.5,114.1 100.5,113.1 102.3,111.3 102.3,97.1 102.3,96.2 101.6,95.5 99.8,95.5 98.8,95.5 97.7,94.4 94.3,94.4 93.8,93.9 93.8,92 93.8,90.6 92.9,89.7 92.4,89.7 91.7,89.7 91.1,89.1 90.5,89.7 89.8,89.7 88.9,89.7 88.6,90
RW on Top Layer "Bottom Layer-W" (hatched 90Degree grid 0.2 track 0.2, remove dead copper, pour order 66): 97.446,93.146 99,94.7 100.3,94.7 100.8,94.7 101.3,94.2 101.3,86.8 100.6,86.1 100.2,86.1 98.641,86.1 98.5,86.241 98.5,86.7 98.1,87.1 98.1,89 97.446,89.654
GND on Top Layer "Bottom Layer-W" (hatched 90Degree grid 0.2 track 0.2, remove dead copper, pour order 68): 103.1,91.2 103.8,91.9 108.167,91.9 109,91.067 109,75.668 101.3,74.973 101.3,84.3 103.1,86.1
GND on Top Layer "Bottom Layer-No Net 1" (hatched 90Degree grid 0.2 track 0.2, remove dead copper, pour order 67): 81.8,0.6 75.9,0.6 11.3,0.6 10.6,1.3 10.2,1.7 10.2,4.3 10.2,6.2 7.4,9 0.7,15.7 0.7,21.7 0.7,81.1 1.4,81.8 9.9,81.8 15.9,81.8 23,81.8 25.9,78.9 25.9,71.8 32.3,71.8 35.3,74.8 37.8,77.3 38.9,77.3 39.8,76.4 39.9,76.3 39.9,74 39.9,73.9 40.5,73.3 40.6,73.2 43,73.2 45,73.2 46,74.2 46.298,74.498 46.98,74.498 47.302,74.498 47.4,74.4 47.9,73.9 47.9,71.3 47.9,69.8 45.1,67 44.7,66.6 44.7,64.3 44.7,63.5 44.2,63 43.668,63 44.667,62 47.5,62 48.7,60.8 56,60.8 60.1,56.7 63.6,56.7 68.7,56.7 72.5,52.9 72.5,37.4 73.9,37.4 79.7,31.6 79.7,15.9 79.7,6.7 81.8,4.6 82.4,4 82.4,1.8 82.4,1.2
GND on Top Layer "Bottom Layer-W" (hatched 90Degree grid 0.2 track 0.2, remove dead copper, pour order 71): 9.816,87 9.816,100.5 9.016,101.3 8.816,101.3 6.5,101.3 5.767,100.567 4.9,99.7 4.9,98.767 4.9,86.8 5.616,86.084 5.7,86 7.816,86 9.216,86 9.816,86.6 9.816,87
GND on Bottom Layer "Bottom Layer-No Net 1" (hatched 90Degree grid 0.2 track 0.2, remove dead copper, pour order 50): 77.673,79.027 77.673,80.561 79.696,82.584 92.716,82.584 98.3,77 98.3,73.934 97.999,73.632 87.783,63.417 87.783,40.601 86.399,39.217 85.166,37.984 85.983,37.984 87.783,36.184 87.783,34.917 86.199,33.332 85.983,33.117 83.183,33.117 82.651,32.584 81.883,31.817 81.883,15.417 82.599,14.701 82.783,14.517 82.783,8.417 85.816,5.384 84.651,5.384 79.933,0.667 73.683,0.667 11.233,0.667 10.183,1.717 10.183,6.217 9.599,6.801 0.683,15.717 0.683,81.101 1.399,81.817 31.699,81.817 32.799,80.717 37.379,76.137 50.153,76.137 52.643,78.627 57.293,78.627 57.736,78.184 57.883,78.037 57.883,74.884 58.383,74.384 58.451,74.317 62.416,74.317 64.083,75.984 64.316,76.217 69.183,76.217 70.583,74.817 76.126,74.817 77.693,76.384 77.673,76.404
AGND on Bottom Layer "Top Layer-No Net" (hatched 90Degree grid 0.2 track 0.2, remove dead copper, pour order 62): 74.6,8.567 74.6,4.3 74.8,4.1 75.7,4.1 79.133,4.1 79.2,4.167 79.416,4.383 79.416,4.584 79.416,7.984 78.5,8.9 77.216,8.9 74.933,8.9 74.6,8.567
AGND on Bottom Layer "Top Layer-No Net" (hatched 90Degree grid 0.2 track 0.2, pour order 60): 48.6,64.9 50.896,64.9 52.6,64.9 53.5,64 53.8,63.7 54.7,63.7 55,63.7 56,64.7 58.6,64.7 78.7,64.7 79,64.4 79,63.9 79,63.6 78.5,63.1 77.6,62.2 49.8,62.2 48.3,63.7 48.3,63.8 48.3,64.6
VBAT on Bottom Layer "Bottom Layer-No Net 1" (hatched 90Degree grid 0.2 track 0.2, remove dead copper, pour order 41): 99.6,70 102.25,72.65 109.1,72.65 109.1,30.967 109.1,30.567 109.1,23.367 108.5,22.767 104.4,22.767 103.2,23.967 103.2,35.5 101.7,37 99.6,39.1 97.9,39.1 97.8,39.2 97.958,39.358 97.958,68.358
AGND on Bottom Layer "Bottom Layer-No Net 1" (hatched 90Degree grid 0.2 track 0.2, remove dead copper, pour order 54): 29.95,17.9 29.616,18.234 29.616,18.916 29.99,19.29 33.31,19.29 33.5,19.1 34.2,19.1 35,19.1 35.5,18.6 35.5,18.1 35.3,17.9
VBAT on Bottom Layer "Bottom Layer-W" (hatched 90Degree grid 0.2 track 0.2, remove dead copper, pour order 69): 109.1,72.567 109.1,103 107.4,104.7 88.816,104.7 13.8,104.7 11.816,102.716 11.3,102.2 11.3,101.9 11.3,95.816 12.416,94.7 20.216,94.7 101.316,94.7 104.016,92 105,91.016 105,78.167 105,75.4 101.967,72.367 102.135,72.2 108.733,72.2 109.1,72.567
GND on Bottom Layer "Bottom Layer-W" (hatched 90Degree grid 0.2 track 0.2, remove dead copper, pour order 70): 104,76.5 104.4,76.9 104.4,79.2 104.4,90.5 101.7,93.2 100.8,94.1 98.6,94.1 11.6,94.1 10.4,95.3 10.4,97.7 10.4,100.6 9.7,101.3 8,101.3 6.5,101.3 5.6,100.4 4.9,99.7 4.9,93.8 4.9,86.8 6.6,85.1 6.9,84.8 41.3,84.8 91.6,84.8 97.3,79.1 99.9,76.5 103,76.5
PX_W on Bottom Layer "Bottom Layer-W" (hatched 90Degree grid 0.2 track 0.2, remove dead copper, pour order 72): 84.9,113.1 85.6,113.8 85.9,114.1 87.016,114.1 99.5,114.1 102.1,111.5 102.3,111.3 102.3,110.567 102.3,106.567 101.7,105.967 101.433,105.7 87.416,105.7 85.5,105.7 84.9,106.3
PX_V on Bottom Layer "Bottom Layer-W" (hatched 90Degree grid 0.2 track 0.2, remove dead copper, pour order 73): 52.1,113.9 52.55,114.35 52.816,114.35 68.85,114.35 70.4,112.8 70.8,112.4 70.8,109.567 70.8,106.7 70.2,106.1 70,105.9 54.4,105.9 53.4,105.9 52.933,106.367 52.1,107.2 52.1,108.167 52.1,113.9
PX_U on Bottom Layer "Bottom Layer-W" (hatched 90Degree grid 0.2 track 0.2, remove dead copper, pour order 74): 18.3,107.3 18.3,108.567 18.3,113.3 19.016,114.016 19.35,114.35 19.816,114.35 35.05,114.35 36.9,112.5 37.7,111.7 37.7,110.767 37.7,106.767 36.9,105.967 36.433,105.5 22.016,105.5 20.1,105.5 19.033,106.567
GND on Bottom Layer "Bottom Layer-W" (hatched 90Degree grid 0.2 track 0.2, remove dead copper, pour order 75): 79.696,82.584 78.116,82.584 77.7,83 77.7,84.284 78.216,84.8 78.383,84.967 78.4,84.967 74.267,84.967 74.1,84.8 77.4,81.5 77.673,81.227 77.673,80.167 78.377,80.167 78.48,80.27
GND on Bottom Layer "Bottom Layer-W" (hatched 90Degree grid 0.2 track 0.2, remove dead copper, pour order 76): 51.984,77.967 52,77.984 52,78.5 50.4,80.1 49.9,80.6 45.1,80.6 44.167,80.6 39.6,85.167 39.633,85.2 46.016,85.2 45.5,85.2 44.7,84.4 44.3,84 44.3,83.3 44.3,83.2 45.1,82.4 45.5,82 46.8,82 51.867,82 55.5,78.367

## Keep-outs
Keep-Out Layer:
  circle w0.1: c3.5,111.5 r1.75
  circle w0.1: c106.5,111.5 r1.75
  circle w0.1: c3.5,3.5 r1.75
  circle w0.1: c106.5,3.5 r1.75
  lines w0.1: 0,111.5 cw(c3.5,111.5) 3.5,115 ; 0.01,3.5 ccw(c3.51,3.5) 3.51,0 ; 106.51,0 ccw(c106.51,3.5) 110.01,3.5 ; 106.51,115 cw(c106.51,111.5) 110.01,111.5 ; 0,0 110,0 110,115 0,115 0,0

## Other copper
Top Layer:
  rectangle net GND: 43.1,22.71 46.06,23.2
  rectangle net GND: 71.7,19.8 72.3,22.767
  rectangle net AGND: 76.2,65.5 77.8,66.1
  region net GND: 46.335,40.34 46.335,40.654 44.26,40.654 44.26,40.34
  region net GND: 46.35,39.05 46.35,39.44 45.76,39.44 45.76,39.05
  region net GND: 44.54,38.57 44.54,39.38 44.15,39.38 44.15,38.57
  region net GND: 43.74,39.75 43.74,39.95 43.35,39.95 43.35,39.75
  rectangle net DVDD: 39.49,21.47 40.05,27.71
  rectangle net VBAT: 101.016,23.8 105.016,25.2
  rectangle net VBAT: 101.3,21.1 105.016,22.2
  rectangle net VBAT: 102,19.325 103.6,26
  rectangle net VBAT: 101,27.4 103.416,28.5
  rectangle net VBAT: 101.1,30.2 103.5,31.367
  rectangle net VBAT: 101.6,26.167 102.5,32.367
  rectangle net VBAT: 101.75,11.567 104.05,15.4
  rectangle net VBAT: 96.25,11.4 98.55,15.367
  rectangle net VBAT: 94.616,12.6 105.816,14.3
  rectangle net GND: 84.216,26.567 88,28.9
  rectangle net GND: 84.3,21 88.016,23.567
  rectangle net GND: 85.3,19.7 86.7,30.767
  rectangle net GND: 93.4,23.8 97.1,25
  rectangle net GND: 93.4,21.4 97.1,22.4
  rectangle net GND: 94.5,20.1 96.5,25.967
  rectangle net GND: 96.016,26.4 97.2,32.5
  rectangle net GND: 95.1,31 97.6,31.7
  rectangle net GND: 94.9,29.8 96.2,30.5
  rectangle net GND: 95.216,27.9 96.2,28.7
  rectangle net GND: 95.2,26.8 96.1,27.367
  rectangle net GND: 91.6,62.567 95.3,64.167
  rectangle net GND: 92.8,61.3 94.216,65.2
  rectangle net GND: 91.616,41.567 95.2,43.2
  rectangle net GND: 92.816,40.7 94.016,44.2
  rectangle net GND: 44.5,38.6 44.8,39.167
  rectangle net GND: 43.316,38.4 43.9,39.367
  rectangle net GND: 23.816,71.408 24.616,73.726
  region net GND: 7.137,29.92 7.137,28.87 9.737,28.87 9.737,29.92
  region net GND: 7.87,30.689 7.87,28.254 8.737,28.254 8.737,30.689
  rectangle net AGND: 30,5.3 30.2,9
  region net GND: 44.46,39.61 44.46,40.97 43.92,40.97 43.92,39.61
  rectangle net DVDD: 55.6,42.3 56.6,46.7
Bottom Layer:
  rectangle net GND: 31.58,26.37 39.5,34.49
  rectangle net VBAT: 98.777,41.5 103.016,43.167
  rectangle net VBAT: 100.6,40.367 101.8,44.1
  rectangle net VBAT: 100.216,61.4 101.816,65.2
  rectangle net VBAT: 99.016,62.6 103.016,63.9
  rectangle net GND: 7.183,29.151 9.616,29.657
  rectangle net GND: 7.904,28.175 8.626,30.657
  rectangle net DVDD: 23.2,20.7 24,31.8

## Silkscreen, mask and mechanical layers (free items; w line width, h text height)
Top Overlay:
  drawing of 1532 lines, arcs and shapes, not listed
  text "RV" at 58.25,80.72 h1.5
  text "RW" at 89.84,80.73 h2
  text "RU" at 41.56,79.54 h2
  text "IO30" at 10.6,76.447 h2
  text "+3.3V" at 26.6,74.3 h2
  text "GND" at 73.05,74.05 h1.5
  text "IO31" at 10.6,73.907 h2
  text "IVS+" at 61.416,73.92 h1.5
  text "SNV" at 57.87,73.82 h1.5
  text "SNW" at 88.06,73.8 h1.5
  text "IWS+" at 92.016,73.8 h1.5
  text "SNU" at 39.78,72.33 h1.5
  text "IWS+" at 43.32,72.34 h1.5
  text "GND" at 26.6,71.767 h2
  text "IO32" at 10.6,71.367 h2
  text "RXD" at 26.6,69.2 h2
  text "NC" at 10.6,68.827 h2
  text "TXD" at 26.6,66.7 h2
  text "IO34" at 10.6,66.287 h2
  text "IO35" at 10.6,63.747 h2
  text "GND" at 2.016,62.1 h3 r270
  text "IO36" at 10.6,61.207 h2
  text "IO37" at 10.6,58.667 h2
  text "GND" at 31.75,58.35 h2.5
  text "VDDG" at 41.5,58.3 h1.5
  text "RESET" at 26.5,56.767 h1.5
  text "IO38" at 10.6,56.127 h2
  text "IO39" at 10.6,53.587 h2
  text "GND" at 76.77,51.09 h2.5
  text "TRSTN" at 10.6,50.9 h2
  text "XRSTN" at 10.6,48.5 h2
  text "BOOT" at 10.6,45.96 h2
  text "SWG" at 28.5,45.767 h2
  text "SW3" at 51,39.9 h1.5
  text "CPBOT" at 62.7,38.702 h2 r270
  text "CFTOP" at 64.65,38.702 h2 r270
  text "VCP" at 66.6,38.7 h2 r270
  text "GPIO40" at 10.6,35.96 h2
  text "TRSTN" at 3.137,34.454 h1.5 r270
  text "VDD5" at 18.7,33.8 h1.5
  text "IO2   3" at 66.5,32.4 h1.5
  text "3.3V" at 10.284,31.6 h1.5
  text "XRSTn" at 1.67,30.964 h1.5 r270
  text "GND" at 10.384,29 h1.5
  text "NC" at 3.137,27.67 h1.5 r270
  text "RX" at 10.6,26.4 h1.5
  text "SWD" at 1.67,25.28 h1.5 r270
  text "IO17" at 52.6,24.767 h1.5
  text "XIO" at 56.8,24.567 h1.5
  text "TX" at 10.416,23.7 h1.5
  text "SWC" at 3.137,23.07 h1.5 r270
  text "BOOT" at 10.4,21.3 h1.5
  text "DC9" at 40.38,18.03 h1.3
  text "DC11" at 44.81,18.03 h1.3
  text "DC13" at 49.73,18.03 h1.3
  text "IO16" at 53,17.3 h1.5
  text "XIN" at 56.816,17.3 h1.5
  text "DC0" at 31.93,16.75 h1.3
  text "DC1" at 34.78,16.75 h1.3
  text "DC8" at 37.4,16.75 h1.3
  text "DC10" at 42.21,16.75 h1.3
  text "DC12" at 47.46,16.75 h1.3
  text "DVDD" at 17.01,14.393 h1.6
  text "GND" at 70.11,12.341 h2.5
  text "NC" at 33.016,10.4 h1.3 r270
  text "DIV" at 35.556,10.4 h1.3 r270
  text "IU+" at 38.096,10.4 h1.3 r270
  text "IU-" at 40.636,10.4 h1.3 r270
  text "IV+" at 43.176,10.4 h1.3 r270
  text "IV-" at 45.716,10.4 h1.3 r270
  text "IW+" at 48.256,10.4 h1.3 r270
  text "IW-" at 50.796,10.4 h1.3 r270
  text "BOOT" at 8.4,8.5 h2
  text "TRSTn" at 25.33,8.273 h2
  text "GND" at 17.47,1.433 h2
  text "SPD1188.ENGR.20201105" at 56.3,0.9 h3.5
  text "SPD1188.ENGR.20201105" at 10.2,-8.8 h3.5
  text "技术要求：" at 12.479,-12.466 h3
  text "1、PCB板材质Tg：135度；" at 26.142,-15.966 h3
  text "2、上、下层丝印为白色，阻焊为绿色；" at 26.139,-19.875 h3
  text "3、所用板材必须阻燃,成品板CTI大于等于400，吸水率小于5%；；" at 26.142,-23.383 h3
  text "4、符合ROHS/UL/CQC要求" at 26.142,-27.108 h3
  text "5、单板110*115mm，板厚：1.6mm，铜厚:70um；" at 26.142,-30.716 h3
  text "6、过孔是否绿油根据过孔的设置来；" at 26.249,-34.286 h3
  text "7、芯片的引脚中间必须喷绿油，特别是CHIP；" at 26.359,-37.906 h3
  text "8、过孔塞铜，盖绿油。" at 26.159,-41.406 h3
Top Solder:
  rectangle: 93.2,4.2 96.8,7.8
Bottom Solder:
  rectangle: 31.44,24.62 41.656,35.02
  lines w1: 14.2,104.1 106.7,104.1
  lines w1.5: 6.2,88.178 102.9,88.2 ; 6.2,90.389 102.9,90.4 ; 6.2,92.6 101,92.6 102.7,90.9 102.7,77.367 ; 7.3,85.967 100.4,85.967 102.9,85.967 ; 12.816,95.8 107.616,95.8 ; 15.216,98.584 107.7,98.584 ; 17.533,101.367 37.9,101.367 ; 48.467,101.367 71,101.367 ; 79.067,101.367 107.5,101.367 ; 88,92.267 94.2,86.067 94.2,83.8 ; 92.7,92.3 97.016,87.984 97.016,81.4 ; 96.258,92.542 100.2,88.6 100.2,78.367 ; 97.616,103.8 102.3,99.116 102.3,95.8 ; 100.816,45.8 100.816,60.583 ; 101.9,103.967 106.016,99.852 106.016,76.1 ; 105,24.5 105,73.116 ; 106.416,103.8 108,102.216 108,25.184 107.816,25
